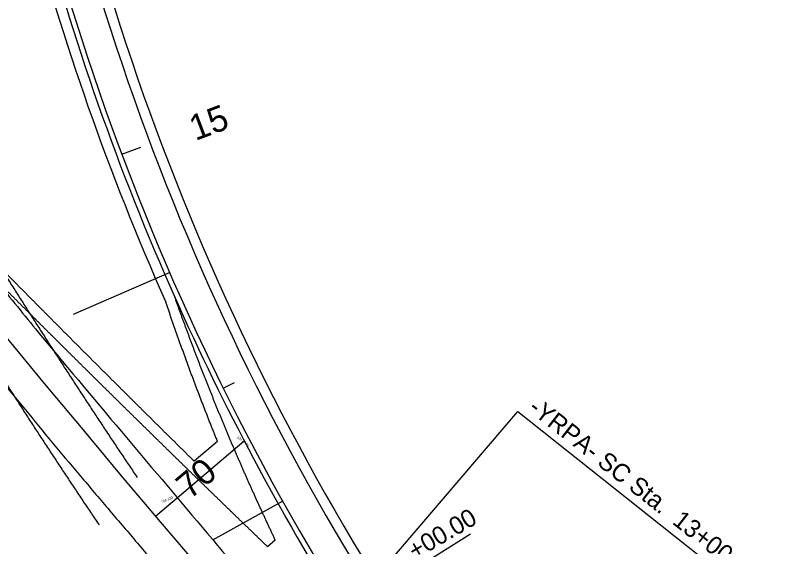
# Model space of a CAD drawing. Extents: x 1778969 to 1790720, y 807089 to 817794.
# Drawn here: x 1782468.8 to 1782767.6, y 812671.8 to 812880.2 of the extents above; entities that cross this region are included whole.
import ezdxf

# ---------------------------------------------------------------- set-up
doc = ezdxf.new("R2010")
doc.units = 0
for name, color, linetype in [('Prop Dimension', 7, 'Continuous'), ('Prop Dimension Text', 7, 'Continuous'), ('Prop EOT', 7, 'Continuous'), ('Prop Horizontal Alignment', 7, 'Continuous'), ('Prop Horizontal Alignment Station Label', 7, 'Continuous'), ('Prop Horizontal Alignment Tick Label', 7, 'Continuous'), ('Prop Horizontal Alignment Tick Large', 7, 'Continuous'), ('Prop Horizontal Alignment Tick Small', 7, 'Continuous'), ('Prop Lane Lines', 7, 'Continuous'), ('Prop Paved Shoulder', 7, 'Continuous'), ('Scratch_Level_1', 7, 'Continuous'), ('Scratch_Level_3', 7, 'Continuous'), ('Scratch_Level_4', 7, 'Continuous')]:
    doc.layers.add(name, color=color, linetype=linetype)

msp = doc.modelspace()

# ---------------------------------------------------------------- linework, layer by layer
at = {"layer": 'Prop Dimension'}
msp.add_line((1782616.51, 812657.58), (1782647.41, 812676.93), dxfattribs=at)
at = {"layer": 'Prop EOT'}
msp.add_line((1782570.86, 812674.41), (1782567.82, 812671.82), dxfattribs=at)
for radius, end in [(1002, 204.03422), (988, 212.05563)]:
    msp.add_arc((1783446.68, 813177.45), radius, 185.30484, end, dxfattribs=at)
msp.add_open_spline([(1781718, 813799.07), (1781725.25, 813787.64), (1781732.32, 813776.09), (1781739.53, 813764.62), (1781748.41, 813750.49), (1781757.28, 813736.36), (1781766.17, 813722.23), (1781775.05, 813708.11), (1781784.04, 813694.06), (1781792.91, 813679.93), (1781801.78, 813665.79), (1781810.64, 813651.64), (1781819.51, 813637.51), (1781828.35, 813623.41), (1781837.2, 813609.31), (1781846.04, 813595.21), (1781854.91, 813581.09), (1781863.8, 813566.98), (1781872.77, 813552.92), (1781881.67, 813538.97), (1781890.62, 813525.06), (1781899.56, 813511.14), (1781909.02, 813496.43), (1781918.41, 813481.67), (1781927.98, 813467.03), (1781936.67, 813453.72), (1781945.44, 813440.46), (1781954.18, 813427.18), (1781963.4, 813413.19), (1781972.62, 813399.19), (1781981.85, 813385.2), (1781991.28, 813370.91), (1782000.79, 813356.66), (1782010.37, 813342.46), (1782019.44, 813329.02), (1782028.6, 813315.64), (1782037.78, 813302.29), (1782047.33, 813288.38), (1782056.88, 813274.48), (1782066.55, 813260.66), (1782076.08, 813247.05), (1782085.65, 813233.46), (1782095.22, 813219.88), (1782104.86, 813206.2), (1782114.49, 813192.52), (1782124.19, 813178.89), (1782133.79, 813165.38), (1782143.47, 813151.93), (1782153.2, 813138.53), (1782163.03, 813124.99), (1782172.87, 813111.45), (1782182.7, 813097.92), (1782192.49, 813084.44), (1782202.28, 813070.96), (1782212.1, 813057.5), (1782222.19, 813043.65), (1782232.6, 813030.04), (1782242.95, 813016.38), (1782253.03, 813003.08), (1782263.13, 812989.8), (1782273.21, 812976.5), (1782283.25, 812963.25), (1782293.24, 812949.97), (1782303.28, 812936.71), (1782313.15, 812923.68), (1782323.08, 812910.68), (1782333.22, 812897.85), (1782343.55, 812884.78), (1782353.98, 812871.79), (1782364.43, 812858.81), (1782374.92, 812845.79), (1782385.44, 812832.79), (1782395.93, 812819.76), (1782406.63, 812806.47), (1782417.16, 812793.03), (1782427.96, 812779.81), (1782438.52, 812766.89), (1782449.19, 812754.07), (1782459.83, 812741.21), (1782470.24, 812728.63), (1782480.58, 812715.98), (1782491.09, 812703.48), (1782501.82, 812690.7), (1782512.68, 812678.03), (1782523.5, 812665.33), (1782534.27, 812652.67), (1782545.05, 812640.01), (1782555.83, 812627.36), (1782566.67, 812614.64), (1782577.52, 812601.95), (1782588.45, 812589.31), (1782599.39, 812576.64), (1782610.53, 812564.14), (1782621.67, 812551.65), (1782632.74, 812539.22), (1782643.82, 812526.79), (1782655, 812514.46), (1782666.21, 812502.08), (1782677.45, 812489.72), (1782688.69, 812477.37), (1782699.92, 812465.03), (1782711.15, 812452.71), (1782722.41, 812440.4), (1782733.64, 812428.12), (1782744.98, 812415.94), (1782756.33, 812403.76), (1782767.99, 812391.23), (1782779.7, 812378.74), (1782791.5, 812366.34), (1782803.09, 812354.16), (1782814.85, 812342.15), (1782826.46, 812330), (1782838.01, 812317.9), (1782849.46, 812305.7), (1782861.02, 812293.59), (1782872.17, 812281.92), (1782883.35, 812270.25), (1782894.68, 812258.74), (1782906.41, 812246.83), (1782918.19, 812234.96), (1782929.97, 812223.1), (1782941.62, 812211.36), (1782953.24, 812199.57), (1782964.97, 812187.91), (1782968.29, 812184.62), (1782971.62, 812181.35), (1782974.95, 812178.08)], degree=3, dxfattribs=at)
for points in [[(1782496.11, 812741.79), (1782495.63, 812742.27), (1782495.15, 812742.74), (1782494.67, 812743.22), (1782494.18, 812743.7), (1782493.7, 812744.17), (1782493.22, 812744.65), (1782492.74, 812745.13), (1782492.26, 812745.6), (1782491.78, 812746.08), (1782491.3, 812746.56), (1782490.81, 812747.03), (1782490.33, 812747.51), (1782489.85, 812747.99), (1782489.37, 812748.46), (1782488.89, 812748.94), (1782488.41, 812749.42), (1782487.93, 812749.89), (1782487.45, 812750.37), (1782486.97, 812750.85), (1782486.48, 812751.33), (1782486, 812751.8), (1782485.52, 812752.28), (1782485.04, 812752.76), (1782484.56, 812753.23), (1782484.08, 812753.71), (1782483.6, 812754.19), (1782483.12, 812754.67), (1782482.64, 812755.14), (1782482.16, 812755.62), (1782481.68, 812756.1), (1782481.2, 812756.58), (1782480.72, 812757.06), (1782480.24, 812757.53), (1782479.76, 812758.01), (1782479.27, 812758.49), (1782478.79, 812758.97), (1782478.31, 812759.45), (1782477.83, 812759.92), (1782477.35, 812760.4), (1782476.87, 812760.88), (1782476.39, 812761.36), (1782475.91, 812761.84), (1782475.43, 812762.31), (1782474.95, 812762.79), (1782474.47, 812763.27), (1782473.99, 812763.75), (1782473.51, 812764.23), (1782473.03, 812764.71), (1782472.55, 812765.19), (1782472.07, 812765.66), (1782471.59, 812766.14), (1782471.11, 812766.62), (1782470.63, 812767.1), (1782470.15, 812767.58), (1782469.67, 812768.06), (1782469.2, 812768.54), (1782468.72, 812769.02), (1782468.24, 812769.49), (1782467.76, 812769.97), (1782467.28, 812770.45), (1782466.8, 812770.93), (1782466.32, 812771.41), (1782465.84, 812771.89), (1782465.36, 812772.37), (1782464.88, 812772.85), (1782464.4, 812773.33), (1782463.92, 812773.81), (1782463.44, 812774.29), (1782462.96, 812774.77), (1782462.49, 812775.25), (1782462.01, 812775.73), (1782461.53, 812776.21), (1782460.57, 812777.17)], [(1782549.95, 812721.47), (1782549.69, 812722.12), (1782549.42, 812722.76), (1782549.16, 812723.4), (1782548.89, 812724.04), (1782548.63, 812724.69), (1782548.37, 812725.33), (1782548.1, 812725.97), (1782547.84, 812726.61), (1782547.58, 812727.26), (1782547.32, 812727.9), (1782547.06, 812728.54), (1782546.8, 812729.19), (1782546.54, 812729.83), (1782546.28, 812730.47), (1782546.02, 812731.12), (1782545.76, 812731.76), (1782545.5, 812732.41), (1782545.24, 812733.05), (1782544.99, 812733.7), (1782544.73, 812734.34), (1782544.47, 812734.98), (1782544.22, 812735.63), (1782543.96, 812736.27), (1782543.71, 812736.92), (1782543.45, 812737.57), (1782543.2, 812738.21), (1782542.94, 812738.86), (1782542.69, 812739.5), (1782542.44, 812740.15), (1782542.19, 812740.79), (1782541.94, 812741.44), (1782541.68, 812742.09), (1782541.43, 812742.73), (1782541.18, 812743.38), (1782540.93, 812744.03), (1782540.68, 812744.67), (1782540.44, 812745.32), (1782540.19, 812745.97), (1782539.94, 812746.61), (1782539.69, 812747.26), (1782539.44, 812747.91), (1782539.2, 812748.56), (1782538.95, 812749.21), (1782538.71, 812749.85), (1782538.46, 812750.5), (1782538.22, 812751.15), (1782537.97, 812751.8), (1782537.73, 812752.45), (1782537.48, 812753.1), (1782537.24, 812753.74), (1782537, 812754.39), (1782536.76, 812755.04), (1782536.52, 812755.69), (1782536.27, 812756.34), (1782536.03, 812756.99), (1782535.79, 812757.64), (1782535.55, 812758.29), (1782535.31, 812758.94), (1782535.08, 812759.59), (1782534.84, 812760.24), (1782534.6, 812760.89), (1782534.36, 812761.54), (1782534.13, 812762.19), (1782533.89, 812762.84), (1782533.65, 812763.49), (1782533.42, 812764.14), (1782533.18, 812764.79), (1782532.95, 812765.45), (1782532.71, 812766.1), (1782532.48, 812766.75), (1782532.25, 812767.4), (1782532.01, 812768.05), (1782531.55, 812769.35)], [(1782531.86, 812706.67), (1782531.38, 812707.14), (1782530.89, 812707.62), (1782530.41, 812708.09), (1782529.93, 812708.56), (1782529.44, 812709.04), (1782528.96, 812709.51), (1782528.47, 812709.98), (1782527.99, 812710.46), (1782527.5, 812710.93), (1782527.02, 812711.4), (1782526.54, 812711.88), (1782526.05, 812712.35), (1782525.57, 812712.82), (1782525.08, 812713.3), (1782524.6, 812713.77), (1782524.12, 812714.24), (1782523.63, 812714.72), (1782523.15, 812715.19), (1782522.66, 812715.66), (1782522.18, 812716.14), (1782521.7, 812716.61), (1782521.21, 812717.09), (1782520.73, 812717.56), (1782520.25, 812718.03), (1782519.76, 812718.51), (1782519.28, 812718.98), (1782518.79, 812719.46), (1782518.31, 812719.93), (1782517.83, 812720.4), (1782517.34, 812720.88), (1782516.86, 812721.35), (1782516.38, 812721.83), (1782515.89, 812722.3), (1782515.41, 812722.78), (1782514.93, 812723.25), (1782514.44, 812723.72), (1782513.96, 812724.2), (1782513.48, 812724.67), (1782513, 812725.15), (1782512.51, 812725.62), (1782512.03, 812726.1), (1782511.55, 812726.57), (1782511.06, 812727.05), (1782510.58, 812727.52), (1782510.1, 812728), (1782509.61, 812728.47), (1782509.13, 812728.95), (1782508.65, 812729.42), (1782508.17, 812729.9), (1782507.68, 812730.37), (1782507.2, 812730.85), (1782506.72, 812731.32), (1782506.24, 812731.8), (1782505.75, 812732.27), (1782505.27, 812732.75), (1782504.79, 812733.22), (1782504.31, 812733.7), (1782503.82, 812734.17), (1782503.34, 812734.65), (1782502.86, 812735.13), (1782502.38, 812735.6), (1782501.89, 812736.08), (1782501.41, 812736.55), (1782500.93, 812737.03), (1782500.45, 812737.5), (1782499.97, 812737.98), (1782499.48, 812738.46), (1782499, 812738.93), (1782498.52, 812739.41), (1782498.04, 812739.88), (1782497.56, 812740.36), (1782497.07, 812740.84), (1782496.59, 812741.31), (1782496.11, 812741.79)], [(1782570.86, 812674.41), (1782570.56, 812675.04), (1782570.27, 812675.67), (1782569.97, 812676.3), (1782569.67, 812676.93), (1782569.37, 812677.57), (1782569.08, 812678.2), (1782568.78, 812678.83), (1782568.48, 812679.46), (1782568.19, 812680.09), (1782567.89, 812680.72), (1782567.6, 812681.35), (1782567.3, 812681.98), (1782567.01, 812682.62), (1782566.72, 812683.25), (1782566.42, 812683.88), (1782566.13, 812684.51), (1782565.84, 812685.15), (1782565.55, 812685.78), (1782565.26, 812686.41), (1782564.97, 812687.04), (1782564.68, 812687.68), (1782564.39, 812688.31), (1782564.1, 812688.95), (1782563.81, 812689.58), (1782563.52, 812690.21), (1782563.23, 812690.85), (1782562.94, 812691.48), (1782562.66, 812692.12), (1782562.37, 812692.75), (1782562.09, 812693.39), (1782561.8, 812694.02), (1782561.51, 812694.66), (1782561.23, 812695.29), (1782560.95, 812695.93), (1782560.66, 812696.56), (1782560.38, 812697.2), (1782560.1, 812697.83), (1782559.81, 812698.47), (1782559.53, 812699.11), (1782559.25, 812699.74), (1782558.97, 812700.38), (1782558.69, 812701.02), (1782558.41, 812701.65), (1782558.13, 812702.29), (1782557.85, 812702.93), (1782557.57, 812703.56), (1782557.29, 812704.2), (1782557.01, 812704.84), (1782556.74, 812705.48), (1782556.46, 812706.12), (1782556.18, 812706.75), (1782555.91, 812707.39), (1782555.63, 812708.03), (1782555.36, 812708.67), (1782555.08, 812709.31), (1782554.81, 812709.95), (1782554.53, 812710.59), (1782554.26, 812711.23), (1782553.99, 812711.86), (1782553.72, 812712.5), (1782553.44, 812713.14), (1782553.17, 812713.78), (1782552.9, 812714.42), (1782552.63, 812715.06), (1782552.36, 812715.7), (1782552.09, 812716.34), (1782551.82, 812716.99), (1782551.55, 812717.63), (1782551.29, 812718.27), (1782551.02, 812718.91), (1782550.75, 812719.55), (1782550.48, 812720.19), (1782550.22, 812720.83), (1782549.95, 812721.47)], [(1782567.82, 812671.81), (1782567.34, 812672.28), (1782566.85, 812672.75), (1782566.36, 812673.22), (1782565.88, 812673.69), (1782565.39, 812674.16), (1782564.9, 812674.63), (1782564.41, 812675.1), (1782563.93, 812675.57), (1782563.44, 812676.04), (1782562.95, 812676.51), (1782562.47, 812676.98), (1782561.98, 812677.45), (1782561.49, 812677.92), (1782561.01, 812678.39), (1782560.52, 812678.86), (1782560.03, 812679.33), (1782559.55, 812679.8), (1782559.06, 812680.27), (1782558.57, 812680.74), (1782558.09, 812681.21), (1782557.6, 812681.68), (1782557.11, 812682.15), (1782556.63, 812682.62), (1782556.14, 812683.09), (1782555.65, 812683.56), (1782555.17, 812684.03), (1782554.68, 812684.5), (1782554.19, 812684.97), (1782553.71, 812685.44), (1782553.22, 812685.91), (1782552.73, 812686.38), (1782552.25, 812686.86), (1782551.76, 812687.33), (1782551.28, 812687.8), (1782550.79, 812688.27), (1782550.3, 812688.74), (1782549.82, 812689.21), (1782549.33, 812689.68), (1782548.85, 812690.15), (1782548.36, 812690.62), (1782547.87, 812691.09), (1782547.39, 812691.57), (1782546.9, 812692.04), (1782546.42, 812692.51), (1782545.93, 812692.98), (1782545.45, 812693.45), (1782544.96, 812693.92), (1782544.48, 812694.39), (1782543.99, 812694.87), (1782543.5, 812695.34), (1782543.02, 812695.81), (1782542.53, 812696.28), (1782542.05, 812696.75), (1782541.56, 812697.23), (1782541.08, 812697.7), (1782540.59, 812698.17), (1782540.11, 812698.64), (1782539.62, 812699.11), (1782539.14, 812699.58), (1782538.65, 812700.06), (1782538.17, 812700.53), (1782537.68, 812701), (1782537.2, 812701.47), (1782536.71, 812701.95), (1782536.23, 812702.42), (1782535.74, 812702.89), (1782535.26, 812703.36), (1782534.77, 812703.84), (1782534.29, 812704.31), (1782533.8, 812704.78), (1782533.32, 812705.25), (1782532.83, 812705.73), (1782532.35, 812706.2), (1782531.86, 812706.67)]]:
    msp.add_spline(points, degree=3, dxfattribs=at)
at = {"layer": 'Prop Horizontal Alignment'}
for centre, radius, start, end in [((1788355.99, 817618.07), 7639.44, 213.341667, 236.008333), ((1783446.68, 813177.45), 1000, 185.30484, 212.05563), ((1786819.89, 816137.48), 5729.58, 212.5, 236.18333)]:
    msp.add_arc(centre, radius, start, end, dxfattribs=at)
at = {"layer": 'Prop Horizontal Alignment Station Label'}
for p, q in [((1782600.12, 812647.85), (1782665.94, 812724.79)), ((1782665.94, 812724.79), (1782761.88, 812648.83))]:
    msp.add_line(p, q, dxfattribs=at)
at = {"layer": 'Prop Horizontal Alignment Tick Large'}
for p, q in [((1782510.6, 812825.67), (1782518.09, 812828.48)), ((1782523.85, 812683.8), (1782529.95, 812688.96))]:
    msp.add_line(p, q, dxfattribs=at)
at = {"layer": 'Prop Horizontal Alignment Tick Small'}
msp.add_line((1782550.39, 812733.97), (1782554.88, 812736.19), dxfattribs=at)
at = {"layer": 'Prop Lane Lines'}
msp.add_arc((1783446.68, 813177.45), 1002, 204.03422, 212.05563, dxfattribs=at)
msp.add_spline([(1782460.57, 812777.17), (1782476.81, 812757.21), (1782510.49, 812717), (1782542.12, 812679.49), (1782574.5, 812641.55), (1782607.39, 812603.57), (1782640.11, 812566.22), (1782672.29, 812530.33), (1782705.88, 812493.21), (1782740.42, 812455.42), (1782773.54, 812419.77), (1782808.36, 812382.53), (1782843.03, 812346.2), (1782876.17, 812311.64), (1782911.51, 812275.08), (1782933.33, 812252.92)], degree=3, dxfattribs=at)
at = {"layer": 'Prop Paved Shoulder'}
msp.add_line((1782548.18, 812713.12), (1782539.01, 812705.37), dxfattribs=at)
for radius, end in [(1006, 204.03422), (984, 212.05563)]:
    msp.add_arc((1783446.68, 813177.45), radius, 185.30484, end, dxfattribs=at)
for points in [[(1782501.45, 812742.59), (1782500.95, 812743.09), (1782500.44, 812743.6), (1782499.93, 812744.1), (1782499.43, 812744.61), (1782498.92, 812745.11), (1782498.42, 812745.62), (1782497.91, 812746.12), (1782497.41, 812746.63), (1782496.9, 812747.13), (1782496.39, 812747.64), (1782495.89, 812748.14), (1782495.38, 812748.65), (1782494.88, 812749.16), (1782494.37, 812749.66), (1782493.87, 812750.17), (1782493.36, 812750.67), (1782492.86, 812751.18), (1782492.35, 812751.68), (1782491.85, 812752.19), (1782491.34, 812752.7), (1782490.84, 812753.2), (1782490.33, 812753.71), (1782489.83, 812754.21), (1782489.32, 812754.72), (1782488.82, 812755.23), (1782488.31, 812755.73), (1782487.81, 812756.24), (1782487.3, 812756.74), (1782486.8, 812757.25), (1782486.29, 812757.76), (1782485.79, 812758.26), (1782485.28, 812758.77), (1782484.78, 812759.28), (1782484.28, 812759.78), (1782483.77, 812760.29), (1782483.27, 812760.8), (1782482.76, 812761.3), (1782482.26, 812761.81), (1782481.75, 812762.32), (1782481.25, 812762.82), (1782480.75, 812763.33), (1782480.24, 812763.84), (1782479.74, 812764.35), (1782479.23, 812764.85), (1782478.73, 812765.36), (1782478.22, 812765.87), (1782477.72, 812766.37), (1782477.22, 812766.88), (1782476.71, 812767.39), (1782476.21, 812767.9), (1782475.71, 812768.4), (1782475.2, 812768.91), (1782474.7, 812769.42), (1782474.19, 812769.93), (1782473.69, 812770.43), (1782473.19, 812770.94), (1782472.68, 812771.45), (1782472.18, 812771.96), (1782471.68, 812772.47), (1782471.17, 812772.97), (1782470.67, 812773.48), (1782470.17, 812773.99), (1782469.66, 812774.5), (1782469.16, 812775.01), (1782468.66, 812775.51), (1782468.15, 812776.02), (1782467.65, 812776.53), (1782467.15, 812777.04), (1782466.65, 812777.55), (1782466.14, 812778.06), (1782465.64, 812778.56), (1782465.14, 812779.07), (1782464.13, 812780.09)], [(1782548.17, 812713.12), (1782547.88, 812713.85), (1782547.58, 812714.58), (1782547.29, 812715.31), (1782547, 812716.04), (1782546.7, 812716.78), (1782546.41, 812717.51), (1782546.12, 812718.24), (1782545.82, 812718.98), (1782545.53, 812719.71), (1782545.24, 812720.44), (1782544.95, 812721.18), (1782544.66, 812721.91), (1782544.38, 812722.64), (1782544.09, 812723.38), (1782543.8, 812724.11), (1782543.51, 812724.85), (1782543.23, 812725.58), (1782542.94, 812726.32), (1782542.66, 812727.05), (1782542.37, 812727.79), (1782542.09, 812728.52), (1782541.8, 812729.26), (1782541.52, 812729.99), (1782541.24, 812730.73), (1782540.96, 812731.47), (1782540.68, 812732.2), (1782540.4, 812732.94), (1782540.12, 812733.67), (1782539.84, 812734.41), (1782539.56, 812735.15), (1782539.28, 812735.88), (1782539, 812736.62), (1782538.73, 812737.36), (1782538.45, 812738.1), (1782538.18, 812738.83), (1782537.9, 812739.57), (1782537.63, 812740.31), (1782537.35, 812741.05), (1782537.08, 812741.79), (1782536.81, 812742.53), (1782536.54, 812743.26), (1782536.26, 812744), (1782535.99, 812744.74), (1782535.72, 812745.48), (1782535.45, 812746.22), (1782535.18, 812746.96), (1782534.92, 812747.7), (1782534.65, 812748.44), (1782534.38, 812749.18), (1782534.11, 812749.92), (1782533.85, 812750.66), (1782533.58, 812751.4), (1782533.32, 812752.14), (1782533.05, 812752.88), (1782532.79, 812753.62), (1782532.53, 812754.36), (1782532.27, 812755.1), (1782532, 812755.84), (1782531.74, 812756.59), (1782531.48, 812757.33), (1782531.22, 812758.07), (1782530.96, 812758.81), (1782530.7, 812759.55), (1782530.45, 812760.3), (1782530.19, 812761.04), (1782529.93, 812761.78), (1782529.67, 812762.52), (1782529.42, 812763.27), (1782529.16, 812764.01), (1782528.91, 812764.75), (1782528.66, 812765.49), (1782528.4, 812766.24), (1782527.9, 812767.73)], [(1782539.01, 812705.37), (1782538.5, 812705.87), (1782537.99, 812706.37), (1782537.48, 812706.87), (1782536.97, 812707.38), (1782536.46, 812707.88), (1782535.96, 812708.38), (1782535.45, 812708.88), (1782534.94, 812709.38), (1782534.43, 812709.88), (1782533.92, 812710.38), (1782533.41, 812710.88), (1782532.9, 812711.39), (1782532.39, 812711.89), (1782531.89, 812712.39), (1782531.38, 812712.89), (1782530.87, 812713.39), (1782530.36, 812713.9), (1782529.85, 812714.4), (1782529.34, 812714.9), (1782528.84, 812715.4), (1782528.33, 812715.9), (1782527.82, 812716.41), (1782527.31, 812716.91), (1782526.8, 812717.41), (1782526.29, 812717.91), (1782525.79, 812718.41), (1782525.28, 812718.92), (1782524.77, 812719.42), (1782524.26, 812719.92), (1782523.75, 812720.42), (1782523.25, 812720.93), (1782522.74, 812721.43), (1782522.23, 812721.93), (1782521.72, 812722.44), (1782521.22, 812722.94), (1782520.71, 812723.44), (1782520.2, 812723.94), (1782519.69, 812724.45), (1782519.19, 812724.95), (1782518.68, 812725.45), (1782518.17, 812725.96), (1782517.66, 812726.46), (1782517.16, 812726.96), (1782516.65, 812727.47), (1782516.14, 812727.97), (1782515.64, 812728.47), (1782515.13, 812728.98), (1782514.62, 812729.48), (1782514.11, 812729.98), (1782513.61, 812730.49), (1782513.1, 812730.99), (1782512.59, 812731.49), (1782512.09, 812732), (1782511.58, 812732.5), (1782511.07, 812733.01), (1782510.57, 812733.51), (1782510.06, 812734.01), (1782509.55, 812734.52), (1782509.05, 812735.02), (1782508.54, 812735.53), (1782508.03, 812736.03), (1782507.53, 812736.53), (1782507.02, 812737.04), (1782506.51, 812737.54), (1782506.01, 812738.05), (1782505.5, 812738.55), (1782504.99, 812739.06), (1782504.49, 812739.56), (1782503.98, 812740.06), (1782503.48, 812740.57), (1782502.97, 812741.07), (1782502.46, 812741.58), (1782501.96, 812742.08), (1782501.45, 812742.59)]]:
    msp.add_spline(points, degree=3, dxfattribs=at)
at = {"layer": 'Scratch_Level_1'}
for p, q in [((1782491.75, 812763), (1782529.35, 812779.32)), ((1782546.37, 812674.47), (1782573.68, 812689.73))]:
    msp.add_line(p, q, dxfattribs=at)
at = {"layer": 'Scratch_Level_3'}
for p, q in [((1782532.38, 812691.01), (1782558.68, 812713.27)), ((1782523.85, 812683.8), (1782532.38, 812691.01))]:
    msp.add_line(p, q, dxfattribs=at)
at = {"layer": 'Scratch_Level_4'}
for points in [[(1782409.36, 812867.75), (1782410.78, 812865.45), (1782412.2, 812863.15), (1782413.61, 812860.85), (1782415.03, 812858.54), (1782416.45, 812856.24), (1782417.87, 812853.94), (1782419.28, 812851.64), (1782420.7, 812849.34), (1782422.12, 812847.04), (1782423.54, 812844.74), (1782424.96, 812842.44), (1782426.38, 812840.14), (1782427.8, 812837.84), (1782429.22, 812835.54), (1782430.64, 812833.24), (1782432.06, 812830.94), (1782433.49, 812828.65), (1782434.91, 812826.35), (1782436.33, 812824.05), (1782437.76, 812821.75), (1782439.18, 812819.46), (1782440.61, 812817.16), (1782442.03, 812814.87), (1782443.46, 812812.57), (1782444.89, 812810.28), (1782446.32, 812807.98), (1782447.75, 812805.69), (1782449.18, 812803.4), (1782450.61, 812801.1), (1782452.05, 812798.81), (1782453.48, 812796.52), (1782454.91, 812794.23), (1782456.35, 812791.94), (1782457.79, 812789.65), (1782459.23, 812787.37), (1782460.67, 812785.08), (1782462.11, 812782.79), (1782463.55, 812780.51), (1782465, 812778.22), (1782466.44, 812775.94), (1782467.89, 812773.66), (1782469.34, 812771.37), (1782470.79, 812769.09), (1782472.24, 812766.81), (1782473.69, 812764.53), (1782475.15, 812762.26), (1782476.6, 812759.98), (1782478.06, 812757.7), (1782479.52, 812755.43), (1782480.98, 812753.16), (1782482.44, 812750.88), (1782483.91, 812748.61), (1782485.38, 812746.34), (1782486.84, 812744.07), (1782488.31, 812741.81), (1782489.79, 812739.54), (1782491.26, 812737.27), (1782492.74, 812735.01), (1782494.22, 812732.75), (1782495.7, 812730.49), (1782497.18, 812728.23), (1782498.67, 812725.97), (1782500.15, 812723.71), (1782501.64, 812721.46), (1782503.13, 812719.2), (1782504.63, 812716.95), (1782506.12, 812714.7), (1782507.62, 812712.45), (1782509.12, 812710.2), (1782510.63, 812707.96), (1782512.13, 812705.71), (1782513.64, 812703.47), (1782515.15, 812701.23), (1782516.67, 812698.99)], [(1782394.41, 812849.13), (1782395.82, 812846.83), (1782397.24, 812844.53), (1782398.66, 812842.23), (1782400.08, 812839.93), (1782401.49, 812837.63), (1782402.91, 812835.33), (1782404.33, 812833.03), (1782405.75, 812830.73), (1782407.17, 812828.43), (1782408.59, 812826.13), (1782410, 812823.83), (1782411.42, 812821.53), (1782412.84, 812819.23), (1782414.27, 812816.93), (1782415.69, 812814.63), (1782417.11, 812812.33), (1782418.53, 812810.03), (1782419.95, 812807.73), (1782421.38, 812805.44), (1782422.8, 812803.14), (1782424.23, 812800.84), (1782425.65, 812798.55), (1782427.08, 812796.25), (1782428.51, 812793.96), (1782429.93, 812791.66), (1782431.36, 812789.37), (1782432.79, 812787.07), (1782434.22, 812784.78), (1782435.66, 812782.49), (1782437.09, 812780.2), (1782438.52, 812777.91), (1782439.96, 812775.62), (1782441.4, 812773.33), (1782442.83, 812771.04), (1782444.27, 812768.75), (1782445.71, 812766.46), (1782447.15, 812764.18), (1782448.6, 812761.89), (1782450.04, 812759.61), (1782451.49, 812757.32), (1782452.93, 812755.04), (1782454.38, 812752.76), (1782455.83, 812750.48), (1782457.28, 812748.2), (1782458.74, 812745.92), (1782460.19, 812743.64), (1782461.65, 812741.37), (1782463.1, 812739.09), (1782464.56, 812736.81), (1782466.02, 812734.54), (1782467.49, 812732.27), (1782468.95, 812730), (1782470.42, 812727.73), (1782471.89, 812725.46), (1782473.36, 812723.19), (1782474.83, 812720.92), (1782476.31, 812718.66), (1782477.78, 812716.4), (1782479.26, 812714.13), (1782480.74, 812711.87), (1782482.22, 812709.61), (1782483.71, 812707.35), (1782485.2, 812705.1), (1782486.69, 812702.84), (1782488.18, 812700.59), (1782489.67, 812698.34), (1782491.17, 812696.09), (1782492.67, 812693.84), (1782494.17, 812691.59), (1782495.67, 812689.34), (1782497.18, 812687.1), (1782498.69, 812684.86), (1782500.2, 812682.62), (1782501.71, 812680.38)]]:
    msp.add_spline(points, degree=3, dxfattribs=at)

# ---------------------------------------------------------------- texts
at = {"layer": 'Prop Dimension Text'}
msp.add_text('+00.00', height=7, rotation=30.2341, dxfattribs=at).set_placement((1782625.6, 812666.64))
at = {"layer": 'Prop Horizontal Alignment Station Label'}
msp.add_text('-YRPA- SC Sta.  13+00.00', height=7, rotation=321.9589, dxfattribs=at).set_placement((1782669.7, 812725.3))
at = {"layer": 'Prop Horizontal Alignment Tick Label'}
for s, rotation, p in [('15', 20.5965, (1782539.5, 812830.84)), ('70', 40.2328, (1782537.35, 812690.11))]:
    msp.add_text(s, height=10, rotation=rotation, dxfattribs=at).set_placement(p)
at = {"layer": 'Scratch_Level_3'}
for s, rotation, p in [('13+77.81', 321.6309, (1782555.73, 812714.56)), ('766.133', 24.5782, (1782526.35, 812688.8))]:
    msp.add_text(s, height=1, rotation=rotation, dxfattribs=at).set_placement(p)

doc.saveas('drawing.dxf')
